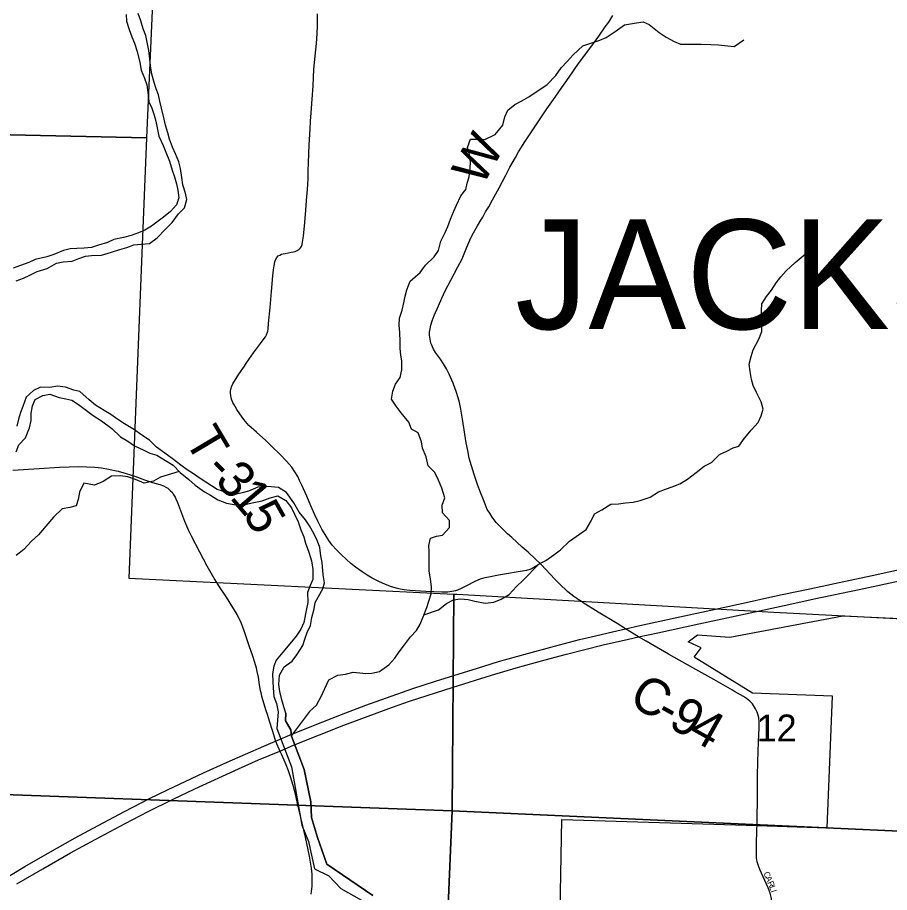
# Model space of a CAD drawing. Extents: x 0 to 34, y 0 to 22.
# Drawn here: x 3.441 to 4.796, y 18.381 to 19.741 of the extents above; entities that cross this region are included whole.
import ezdxf

# ---------------------------------------------------------------- set-up
doc = ezdxf.new("R2010")
doc.units = 0
for name, color, linetype in [('GM_X_City_Street', 7, 'Continuous'), ('GM_X_City_Street_Text', 7, 'Continuous'), ('GM_X_Corporation', 7, 'Continuous'), ('GM_X_County_Road', 7, 'Continuous'), ('GM_X_County_Road_Text', 7, 'Continuous'), ('GM_X_Minor_River', 7, 'Continuous'), ('GM_X_Section', 7, 'Continuous'), ('GM_X_Section_Text', 7, 'Continuous'), ('GM_X_State_Route', 7, 'Continuous'), ('GM_X_Township_Road', 7, 'Continuous'), ('GM_X_Township_Road_Text', 7, 'Continuous'), ('GM_X_Township_Text', 7, 'Continuous')]:
    doc.layers.add(name, color=color, linetype=linetype)

msp = doc.modelspace()

# ---------------------------------------------------------------- linework, layer by layer
at = {"layer": 'GM_X_City_Street'}
msp.add_lwpolyline([(4.6123, 18.3277), (4.6134, 18.3522), (4.6135, 18.3645), (4.6129, 18.3706), (4.6124, 18.3736), (4.6108, 18.3794), (4.6075, 18.388), (4.5998, 18.4049), (4.5947, 18.4162), (4.5925, 18.422), (4.5907, 18.4281), (4.5897, 18.4343), (4.5893, 18.4405), (4.5894, 18.453), (4.5903, 18.4799), (4.5904, 18.4842)], dxfattribs=at)
at = {"layer": 'GM_X_Corporation'}
msp.add_lwpolyline([(4.9748, 17.7073), (4.5871, 17.7299), (4.5956, 17.9659), (4.2619, 17.827), (4.283, 18.2672), (4.2872, 18.4939), (4.5904, 18.485), (4.6993, 18.4813), (4.7077, 18.686), (4.5833, 18.6907), (4.4929, 18.7467), (4.5036, 18.7609), (4.4834, 18.7705), (4.4977, 18.7812), (4.5483, 18.7776), (4.7237, 18.8109), (5.1009, 18.7931)], dxfattribs=at)
at = {"layer": 'GM_X_County_Road'}
for points in [[(4.2532, 18.8921), (4.2462, 18.899), (4.2348, 18.9095), (4.2255, 18.9177), (4.2095, 18.9324), (4.2028, 18.9381), (4.1936, 18.9471), (4.1851, 18.956), (4.1789, 18.964), (4.1749, 18.9701), (4.1712, 18.9761), (4.1676, 18.9842), (4.165, 18.991), (4.1605, 19.0026), (4.156, 19.0149), (4.151, 19.0302), (4.1467, 19.0439), (4.1431, 19.0559), (4.1407, 19.0676), (4.1385, 19.0798), (4.136, 19.093), (4.1327, 19.1162), (4.1298, 19.1318), (4.1278, 19.1421), (4.1261, 19.1495), (4.1234, 19.1581), (4.1224, 19.1609), (4.1214, 19.1638), (4.118, 19.1723), (4.1119, 19.1864), (4.1078, 19.1946), (4.1032, 19.2027), (4.0984, 19.2097), (4.0906, 19.2203), (4.0876, 19.2255), (4.0858, 19.2289), (4.0847, 19.2316), (4.0836, 19.2348), (4.0821, 19.241), (4.0815, 19.2471), (4.0815, 19.2517), (4.0821, 19.2569), (4.0835, 19.2627), (4.0857, 19.2695), (4.0887, 19.2775), (4.0953, 19.2928), (4.1006, 19.3046), (4.1059, 19.3158), (4.1145, 19.3327), (4.1256, 19.3533), (4.1319, 19.3656), (4.1391, 19.384), (4.1456, 19.3981), (4.1498, 19.4063), (4.1558, 19.4169), (4.1612, 19.426), (4.1642, 19.4307), (4.1686, 19.4385), (4.1733, 19.4465), (4.1794, 19.4573), (4.1895, 19.4759), (4.1947, 19.486), (4.1997, 19.4957), (4.2064, 19.5081), (4.2148, 19.5232), (4.2199, 19.5322), (4.2243, 19.5393), (4.2286, 19.5458), (4.2525, 19.5819), (4.2636, 19.5989), (4.2765, 19.6169), (4.2832, 19.6266), (4.2984, 19.6483), (4.3129, 19.6691), (4.332, 19.6947), (4.3444, 19.7119), (4.3545, 19.7263), (4.3599, 19.7336), (4.3632, 19.7387), (4.3662, 19.7441)], [(3.4336, 19.0374), (3.4746, 19.0397), (3.5064, 19.0416), (3.5362, 19.0427), (3.5489, 19.0424), (3.5612, 19.0418), (3.5714, 19.0406), (3.5825, 19.0389), (3.5973, 19.0355), (3.6097, 19.0322), (3.6236, 19.0277), (3.6385, 19.0221), (3.6506, 19.018), (3.6622, 19.015), (3.6678, 19.0129), (3.6717, 19.0108), (3.6744, 19.009), (3.6769, 19.0071), (3.6789, 19.005), (3.6812, 19.0027), (3.6831, 19.0001), (3.6858, 18.9952), (3.6872, 18.9924), (3.6897, 18.9867), (3.7008, 18.9577), (3.7068, 18.9434), (3.7109, 18.9351), (3.7238, 18.9103), (3.7355, 18.8884), (3.7475, 18.8668), (3.7535, 18.8572), (3.7653, 18.8395), (3.7738, 18.8264), (3.7818, 18.813), (3.7862, 18.8048), (3.7888, 18.7993), (3.793, 18.7877), (3.8011, 18.763), (3.8055, 18.7503), (3.8096, 18.7386), (3.8121, 18.7299), (3.813, 18.7244), (3.8148, 18.7153), (3.8168, 18.7034), (3.8184, 18.6945), (3.819, 18.6915), (3.8202, 18.6857), (3.8238, 18.674), (3.8264, 18.6652), (3.8293, 18.6564), (3.8319, 18.6475), (3.8367, 18.6329), (3.8402, 18.6211), (3.842, 18.6161), (3.8434, 18.6123), (3.8471, 18.6038), (3.8487, 18.6005), (3.8511, 18.5954), (3.8551, 18.587), (3.8582, 18.5796), (3.8617, 18.5704), (3.8649, 18.5609), (3.869, 18.5477), (3.872, 18.5359), (3.8757, 18.5191), (3.8882, 18.4664), (3.8941, 18.4369), (3.8972, 18.4185), (3.8982, 18.4092), (3.8985, 18.3999), (3.8982, 18.3905), (3.8969, 18.3781)], [(4.311, 18.837), (4.3102, 18.8375), (4.3059, 18.8407), (4.3012, 18.8443), (4.2964, 18.8482), (4.294, 18.8502), (4.2851, 18.8587), (4.2763, 18.8677), (4.255, 18.8903), (4.2532, 18.8921)], [(4.5522, 18.695), (4.5233, 18.7117), (4.4908, 18.7299), (4.4529, 18.7511), (4.418, 18.7712), (4.4064, 18.7781), (4.3993, 18.7823), (4.386, 18.7906), (4.3729, 18.7987), (4.3437, 18.8165), (4.3201, 18.8311), (4.3175, 18.8328), (4.3149, 18.8344), (4.3125, 18.8359), (4.311, 18.837)], [(4.5904, 18.4842), (4.5906, 18.4939), (4.591, 18.528), (4.5909, 18.5622), (4.5916, 18.5839), (4.5928, 18.615), (4.5939, 18.6367), (4.5938, 18.6459), (4.5931, 18.652), (4.5917, 18.6579), (4.5907, 18.6608), (4.5882, 18.6663), (4.585, 18.6715), (4.5832, 18.6739), (4.579, 18.6783), (4.5742, 18.682), (4.5691, 18.6855), (4.5551, 18.6933), (4.5522, 18.695)]]:
    msp.add_lwpolyline(points, dxfattribs=at)
at = {"layer": 'GM_X_Minor_River'}
for points in [[(3.6097, 19.7453), (3.6105, 19.7354), (3.6147, 19.7221), (3.6189, 19.7107), (3.6228, 19.7009), (3.627, 19.688), (3.6309, 19.6709), (3.6332, 19.6592), (3.6382, 19.6466), (3.642, 19.636), (3.644, 19.6208), (3.6452, 19.6095), (3.6497, 19.6), (3.6536, 19.589), (3.6559, 19.5795), (3.6606, 19.5564), (3.6674, 19.542), (3.6717, 19.5313), (3.677, 19.5173), (3.6813, 19.5033), (3.6851, 19.4934), (3.6882, 19.4824), (3.6901, 19.4726), (3.6917, 19.4604), (3.6883, 19.4498), (3.6789, 19.4391), (3.6679, 19.4303), (3.6494, 19.4166), (3.6388, 19.4101), (3.6289, 19.4063), (3.6179, 19.4021), (3.6058, 19.399), (3.5906, 19.3955), (3.5808, 19.3913), (3.5668, 19.3867), (3.5558, 19.3833), (3.5448, 19.3825), (3.5334, 19.3817), (3.5228, 19.3813), (3.5126, 19.3786), (3.4974, 19.3724), (3.4868, 19.369), (3.4682, 19.3644), (3.4584, 19.3598), (3.4459, 19.3552), (3.4345, 19.3514)], [(3.4388, 19.3316), (3.4501, 19.3358), (3.4604, 19.3404), (3.4717, 19.3458), (3.4869, 19.3508), (3.5016, 19.3588), (3.5122, 19.3611), (3.5259, 19.3623), (3.5361, 19.3661), (3.5467, 19.3696), (3.5562, 19.3711), (3.5718, 19.3716), (3.5873, 19.3762), (3.5998, 19.3804), (3.6108, 19.3835), (3.6218, 19.3877), (3.6332, 19.3885), (3.6464, 19.3896), (3.6582, 19.3984), (3.6714, 19.4125), (3.6812, 19.4224), (3.6914, 19.4354), (3.7005, 19.4449), (3.7042, 19.4578), (3.7023, 19.4677), (3.6977, 19.4809), (3.6965, 19.4919), (3.6942, 19.506), (3.6915, 19.5166), (3.6865, 19.5287), (3.6819, 19.5393), (3.6773, 19.5519), (3.6749, 19.5617), (3.6711, 19.5735), (3.6688, 19.583), (3.6649, 19.5997), (3.6622, 19.6107), (3.6599, 19.6205), (3.6565, 19.63), (3.6534, 19.6399), (3.6499, 19.6528), (3.6476, 19.6657), (3.6468, 19.6767), (3.6452, 19.6896), (3.6433, 19.6998), (3.6402, 19.7127), (3.6363, 19.7233), (3.6325, 19.7355), (3.6287, 19.7472)], [(4.3338, 19.7017), (4.3459, 19.7056), (4.3558, 19.7098), (4.3698, 19.7189), (4.3842, 19.7292), (4.3936, 19.7312), (4.4031, 19.7327), (4.4134, 19.7339), (4.4229, 19.7301), (4.4381, 19.7173), (4.4491, 19.7105), (4.4617, 19.7033), (4.4712, 19.6995), (4.5038, 19.6996), (4.5186, 19.6989), (4.5304, 19.6982)], [(3.8946, 18.6619), (3.9059, 18.6718), (3.9134, 18.6863), (3.9187, 18.6977), (3.9247, 18.7114), (3.9391, 18.7183), (3.9509, 18.7202), (3.9626, 18.7229), (3.9729, 18.7222), (3.9824, 18.7211), (3.9918, 18.7215), (4.0036, 18.7242), (4.0183, 18.7345), (4.0274, 18.7448), (4.0342, 18.7546), (4.0425, 18.7657), (4.0516, 18.7782), (4.061, 18.7878), (4.0666, 18.798), (4.0715, 18.8094), (4.0772, 18.8235), (4.0802, 18.8334), (4.0839, 18.8448), (4.0846, 18.8554), (4.083, 18.8683), (4.0807, 18.8801), (4.0807, 18.8972), (4.081, 18.9105), (4.0802, 18.9203), (4.0828, 18.9317), (4.0923, 18.9348), (4.1017, 18.9363), (4.1123, 18.9478), (4.1126, 18.9588), (4.1016, 18.9709), (4.1012, 18.9827), (4.1049, 18.9941), (4.1003, 19.0092), (4.0953, 19.0217), (4.0896, 19.0335), (4.0793, 19.0441), (4.0762, 19.0581), (4.0704, 19.0714), (4.0689, 19.0813), (4.0635, 19.0953), (4.0532, 19.1009), (4.049, 19.1116), (4.0372, 19.1263), (4.0296, 19.1366), (4.0223, 19.1475), (4.0242, 19.1601), (4.0283, 19.1711), (4.0355, 19.181), (4.0384, 19.1932), (4.0384, 19.2068), (4.0368, 19.2163), (4.0357, 19.2262), (4.0356, 19.2372), (4.0352, 19.2512), (4.034, 19.2626), (4.0347, 19.2732), (4.0388, 19.2858), (4.0414, 19.2972), (4.0437, 19.3074), (4.0463, 19.3177), (4.0515, 19.331), (4.0667, 19.3443), (4.075, 19.3558), (4.0886, 19.3687), (4.0953, 19.3786), (4.0991, 19.3931), (4.1059, 19.4064), (4.1096, 19.4159), (4.1141, 19.4276), (4.119, 19.4398), (4.1235, 19.4493), (4.1299, 19.4634), (4.1378, 19.4733), (4.1397, 19.4832), (4.1431, 19.4934), (4.1445, 19.5067), (4.1452, 19.5166), (4.1433, 19.5276), (4.1406, 19.539), (4.1451, 19.5519), (4.155, 19.5515), (4.1675, 19.5512), (4.1834, 19.5592), (4.1951, 19.5737), (4.1985, 19.5862), (4.203, 19.5969), (4.2139, 19.6057), (4.2249, 19.6114), (4.2359, 19.6175), (4.2643, 19.6366), (4.2775, 19.6507), (4.2862, 19.6628), (4.2952, 19.6727), (4.3047, 19.683), (4.3198, 19.6967), (4.3338, 19.7017)], [(4.5304, 19.6982), (4.5548, 19.6956), (4.5699, 19.7059)], [(4.5534, 19.0719), (4.562, 19.0745), (4.5707, 19.0871), (4.582, 19.1), (4.5922, 19.1114), (4.5967, 19.1217), (4.6, 19.1319), (4.5966, 19.1433), (4.5893, 19.1577), (4.5843, 19.1687), (4.582, 19.1782), (4.5797, 19.1907), (4.5781, 19.2021), (4.5815, 19.2138), (4.5845, 19.2241), (4.5931, 19.2408), (4.598, 19.2526), (4.5979, 19.2651), (4.5971, 19.275), (4.5971, 19.2848), (4.5978, 19.2955), (4.6053, 19.3072), (4.6129, 19.3171), (4.62, 19.3282), (4.6271, 19.3377), (4.6358, 19.3472), (4.6498, 19.3598), (4.6652, 19.3731), (4.6777, 19.3841)], [(3.8582, 18.6595), (3.8551, 18.669), (3.8516, 18.68), (3.8485, 18.6933), (3.8473, 18.7039), (3.8484, 18.7187), (3.8556, 18.7313), (3.8681, 18.7404), (3.8749, 18.7499), (3.8843, 18.7644), (3.8877, 18.7743), (3.891, 18.7849), (3.8963, 18.7959), (3.8985, 18.8081), (3.9023, 18.8214), (3.9037, 18.8313), (3.9086, 18.8408), (3.9158, 18.8526), (3.918, 18.8621), (3.9161, 18.8746), (3.9145, 18.8936), (3.9125, 18.9038), (3.911, 18.9167), (3.9071, 18.927), (3.9018, 18.9387), (3.8949, 18.9505), (3.8884, 18.9599), (3.8789, 18.9717), (3.8705, 18.9864), (3.859, 19.0024), (3.8465, 19.0103), (3.8354, 19.0114), (3.8244, 19.0117), (3.8146, 19.0106), (3.8002, 19.0044), (3.79, 19.0017), (3.7767, 18.999), (3.7649, 19.0028), (3.7512, 19.0069), (3.725, 19.0243), (3.7147, 19.0315), (3.7048, 19.0379), (3.6949, 19.0447), (3.6816, 19.0553), (3.6702, 19.0636), (3.6572, 19.0731), (3.6462, 19.084), (3.6325, 19.0927), (3.6226, 19.0999), (3.6074, 19.109), (3.5971, 19.1158), (3.5861, 19.1237), (3.5758, 19.1301), (3.5621, 19.1384), (3.5522, 19.1464), (3.5381, 19.1592), (3.5286, 19.1615), (3.5157, 19.166), (3.5032, 19.1678), (3.4914, 19.1659), (3.4766, 19.1662), (3.4657, 19.1609)], [(3.4387, 19.0659), (3.4429, 19.0765), (3.4534, 19.0872), (3.4594, 19.1028), (3.4621, 19.1142), (3.4624, 19.1256), (3.4642, 19.137), (3.4687, 19.1468), (3.4805, 19.1533), (3.4911, 19.1553), (3.5059, 19.15), (3.5162, 19.1478), (3.5257, 19.1459), (3.5356, 19.1391), (3.5481, 19.13), (3.5584, 19.1221), (3.5717, 19.1138), (3.5877, 19.1017), (3.601, 19.0892), (3.6124, 19.0824), (3.6227, 19.0748), (3.6372, 19.0681), (3.6467, 19.0635), (3.6573, 19.0605), (3.671, 19.0522), (3.6828, 19.045), (3.6938, 19.0333), (3.7072, 19.0227), (3.7171, 19.014), (3.7315, 19.0034), (3.741, 18.9982), (3.7524, 18.991), (3.7657, 18.9857), (3.7802, 18.9831), (3.7923, 18.9831), (3.8056, 18.9866), (3.8211, 18.9897), (3.8336, 18.9939), (3.8458, 18.997), (3.8579, 18.9902), (3.8671, 18.9785), (3.8717, 18.969), (3.877, 18.9569), (3.8816, 18.9443), (3.8862, 18.9333), (3.8886, 18.9239), (3.8939, 18.9095), (3.8978, 18.8962), (3.9001, 18.8825), (3.8998, 18.8673), (3.896, 18.8578), (3.8919, 18.8472), (3.892, 18.8316), (3.8901, 18.8214), (3.886, 18.8005), (3.8815, 18.7898), (3.874, 18.7792), (3.8642, 18.767), (3.8532, 18.754), (3.843, 18.7419), (3.8393, 18.7324), (3.8374, 18.7206), (3.8378, 18.7088), (3.8386, 18.6986), (3.8395, 18.6853), (3.8433, 18.6743), (3.846, 18.6614)], [(3.4657, 19.1609), (3.4543, 19.1506), (3.4494, 19.1361), (3.4457, 19.1266), (3.4427, 19.1164), (3.4401, 19.1054)], [(4.0726, 18.8122), (4.0954, 18.8201), (4.1075, 18.8301), (4.1185, 18.8354), (4.1291, 18.837), (4.1412, 18.8359), (4.1519, 18.8336), (4.1678, 18.8306), (4.1815, 18.8322), (4.1928, 18.8364), (4.2049, 18.8441), (4.2167, 18.8562), (4.2265, 18.8658), (4.2518, 18.8913), (4.262, 18.8966), (4.2745, 18.9058), (4.2847, 18.9134), (4.2991, 18.9267), (4.3248, 18.9451), (4.3323, 18.9576), (4.3376, 18.9694), (4.349, 18.9755), (4.3633, 18.9843), (4.3751, 18.9847), (4.3857, 18.9863), (4.3979, 18.9874), (4.4085, 18.9901), (4.4244, 18.9951), (4.4372, 19.0035), (4.4482, 19.0077), (4.4585, 19.0112), (4.4702, 19.0158), (4.4823, 19.0234), (4.4956, 19.0333), (4.508, 19.0432), (4.5194, 19.049), (4.5322, 19.0615), (4.5432, 19.0665), (4.5534, 19.0719)], [(3.6923, 19.0349), (3.6631, 19.0264), (3.6522, 19.0203), (3.6381, 19.0172), (3.6244, 19.0225), (3.6123, 19.0266), (3.6009, 19.0281), (3.5872, 19.028), (3.574, 19.0196), (3.5607, 19.0139), (3.544, 19.0169), (3.5376, 19.0032), (3.5354, 18.9914), (3.5324, 18.9819), (3.5222, 18.9792), (3.5104, 18.9773), (3.4972, 18.9639), (3.4851, 18.9502), (3.4734, 18.9365), (3.4628, 18.927), (3.4507, 18.9137), (3.439, 18.9045)], [(3.846, 18.6614), (3.844, 18.6355), (3.867, 18.5761), (3.8828, 18.4854), (3.8931, 18.4597), (3.9027, 18.4172), (3.9247, 18.4067), (3.9437, 18.387), (3.9756, 18.3689)], [(3.9934, 18.3758), (3.9216, 18.4249), (3.9075, 18.4662), (3.8979, 18.4973), (3.8967, 18.5215), (3.8867, 18.5716), (3.8668, 18.6235), (3.8656, 18.6333), (3.8576, 18.6477), (3.8582, 18.6595)], [(3.8582, 18.6595), (3.8576, 18.6477), (3.8656, 18.6333), (3.8668, 18.6235), (3.8867, 18.5716), (3.8967, 18.5215), (3.8979, 18.4973), (3.9075, 18.4662), (3.9216, 18.4249), (3.9934, 18.3758)], [(3.8946, 18.6619), (3.8667, 18.6248)]]:
    msp.add_lwpolyline(points, dxfattribs=at)
at = {"layer": 'GM_X_Section'}
for points in [[(3.1703, 20.5686), (3.6876, 20.5473), (3.6799, 20.3833), (3.6562, 19.8796), (3.6414, 19.554), (3.1241, 19.5651)], [(3.1241, 19.5651), (3.6414, 19.554), (3.6343, 19.3746), (3.6142, 18.8692), (4.1194, 18.8444), (4.1166, 18.5074), (3.0927, 18.5447)], [(4.1194, 18.8444), (4.1236, 18.8442), (4.6166, 18.8164), (5.1167, 18.7903), (5.1294, 18.7895), (5.1195, 18.4619), (4.1166, 18.5074)], [(4.1166, 18.5074), (4.0746, 17.5111), (3.0654, 17.5504), (3.0927, 18.5447)], [(4.1166, 18.5074), (5.1195, 18.4619), (5.0805, 17.4591), (4.0746, 17.5111)]]:
    msp.add_lwpolyline(points, close=True, dxfattribs=at)
at = {"layer": 'GM_X_State_Route'}
for points in [[(3.4125, 18.3974), (3.4525, 18.4212), (3.4874, 18.4415), (3.5308, 18.4658), (3.5663, 18.485), (3.6075, 18.5067), (3.6462, 18.5265), (3.674, 18.5403), (3.7301, 18.5668), (3.7669, 18.5834), (3.8237, 18.6083), (3.842, 18.6161), (3.8637, 18.6253), (3.9012, 18.6403), (3.9445, 18.6573), (3.9823, 18.6716), (4.0144, 18.6832), (4.0555, 18.6975), (4.0909, 18.7092), (4.1561, 18.7295), (4.1888, 18.7395), (4.2335, 18.7524), (4.2755, 18.7637), (4.3146, 18.7738), (4.3327, 18.7782), (4.3659, 18.7861), (4.386, 18.7906), (4.4083, 18.7956), (4.4629, 18.8075), (4.5448, 18.8252), (4.5781, 18.8325), (4.6054, 18.8386), (4.6296, 18.8438), (4.6722, 18.8528), (4.7178, 18.8625), (4.7694, 18.8735), (4.8423, 18.8894)], [(3.4401, 18.3941), (3.4803, 18.4176), (3.5236, 18.4421), (3.5617, 18.4631), (3.6083, 18.488), (3.6442, 18.5065), (3.6831, 18.5259), (3.7167, 18.542), (3.7844, 18.573), (3.8157, 18.5867), (3.8487, 18.6005), (3.8701, 18.6095), (3.9104, 18.6259), (3.948, 18.6406), (3.9858, 18.6548), (4.0238, 18.6686), (4.0502, 18.6779), (4.1181, 18.7), (4.1775, 18.7185), (4.2162, 18.7299), (4.2611, 18.7424), (4.2942, 18.751), (4.3514, 18.7654), (4.3907, 18.7747), (4.4064, 18.7781), (4.4363, 18.7845), (4.5, 18.7982), (4.594, 18.8187), (4.6396, 18.8285), (4.6791, 18.8369), (4.749, 18.8519), (4.8188, 18.8669)]]:
    msp.add_lwpolyline(points, dxfattribs=at)
at = {"layer": 'GM_X_Township_Road'}
msp.add_lwpolyline([(4.2532, 18.8921), (4.2496, 18.8897), (4.2437, 18.8859), (4.2409, 18.8842), (4.237, 18.8826), (4.2323, 18.8812), (4.2162, 18.8786), (4.2039, 18.8765), (4.1886, 18.8739), (4.1734, 18.8709), (4.1675, 18.8696), (4.1603, 18.8676), (4.1518, 18.8639), (4.1389, 18.8571), (4.1304, 18.853), (4.1247, 18.8507), (4.1219, 18.8496), (4.1189, 18.8489), (4.1159, 18.8483), (4.1097, 18.8477), (4.1004, 18.8476), (4.0756, 18.8486), (4.0508, 18.8503), (4.0418, 18.8512), (4.0357, 18.8522), (4.0296, 18.8536), (4.0207, 18.8564), (4.012, 18.8597), (4.0035, 18.8635), (3.9924, 18.8692), (3.9844, 18.8738), (3.9765, 18.8789), (3.9665, 18.8862), (3.9592, 18.8921), (3.9523, 18.8982), (3.9436, 18.9064), (3.9368, 18.9133), (3.9302, 18.9207), (3.9247, 18.928), (3.919, 18.9371), (3.9139, 18.9457), (3.9076, 18.9577), (3.9029, 18.9675), (3.8968, 18.9818), (3.8907, 18.9967), (3.8828, 19.0138), (3.8795, 19.0212), (3.8765, 19.0271), (3.8721, 19.0346), (3.8673, 19.0418), (3.8589, 19.0512), (3.8485, 19.0618), (3.8367, 19.0734), (3.8267, 19.0834), (3.8122, 19.0961), (3.8005, 19.1066), (3.793, 19.1159), (3.7867, 19.1246), (3.7821, 19.1314), (3.7792, 19.1363), (3.7773, 19.1397), (3.7757, 19.1426), (3.7748, 19.1449), (3.7736, 19.1477), (3.7729, 19.15), (3.7724, 19.1531), (3.772, 19.1566), (3.772, 19.1599), (3.7734, 19.1666), (3.7757, 19.1715), (3.7851, 19.1863), (3.7936, 19.1989), (3.7968, 19.2042), (3.8077, 19.2193), (3.8189, 19.2342), (3.8242, 19.2419), (3.8262, 19.2445), (3.8279, 19.2473), (3.8292, 19.2503), (3.8299, 19.2531), (3.8304, 19.2564), (3.8313, 19.2653), (3.8339, 19.29), (3.836, 19.3148), (3.8379, 19.3395), (3.8387, 19.3487), (3.8397, 19.3548), (3.8403, 19.3586), (3.8412, 19.3611), (3.8421, 19.364), (3.844, 19.3675), (3.8463, 19.3702), (3.8485, 19.3716), (3.8513, 19.373), (3.8541, 19.3734), (3.857, 19.3742), (3.8663, 19.3759), (3.8699, 19.3764), (3.8728, 19.3772), (3.8758, 19.3785), (3.8786, 19.3806), (3.8807, 19.3826), (3.8825, 19.385), (3.8835, 19.388), (3.8842, 19.3917), (3.8844, 19.3947), (3.8853, 19.4008), (3.8875, 19.4224), (3.8889, 19.4411), (3.8904, 19.4564), (3.8917, 19.4733), (3.8927, 19.49), (3.893, 19.5023), (3.8933, 19.5147), (3.8944, 19.5427), (3.8957, 19.5675), (3.8963, 19.5799), (3.8973, 19.5928), (3.8992, 19.6138), (3.9005, 19.6346), (3.9018, 19.6604), (3.9036, 19.6809), (3.9055, 19.7004), (3.9066, 19.7158), (3.9071, 19.7281), (3.9075, 19.7464)], dxfattribs=at)

# ---------------------------------------------------------------- texts
at = {"layer": 'GM_X_City_Street_Text'}
for s, rotation, p in [('C', 292.816, (4.6001, 18.4107)), ('A', 292.8183, (4.603, 18.4038)), ('R', 292.717, (4.6063, 18.3961)), ('L', 290.2842, (4.6091, 18.3893)), ('I', 288.3658, (4.6114, 18.3831))]:
    msp.add_text(s, height=0.00947, rotation=rotation, dxfattribs=at).set_placement(p)
at = {"layer": 'GM_X_County_Road_Text'}
for s, rotation, p in [('W', 60.5261, (4.1631, 19.4766)), ('C', 329.3716, (4.3886, 18.675)), ('9', 330.8024, (4.4504, 18.639)), ('-', 330.791, (4.4301, 18.6504)), ('4', 330.8151, (4.481, 18.622))]:
    msp.add_text(s, height=0.0568, rotation=rotation, dxfattribs=at).set_placement(p)
at = {"layer": 'GM_X_Section_Text'}
msp.add_text('12', height=0.04186, rotation=0, dxfattribs=at).set_placement((4.5897, 18.6154))
at = {"layer": 'GM_X_Township_Road_Text'}
for s, rotation, p in [('T', 300.7411, (3.6996, 19.0842)), ('-', 314.2634, (3.7302, 19.0361)), ('3', 312.6626, (3.7462, 19.0197)), ('1', 310.34, (3.7695, 18.9945)), ('5', 299.3544, (3.7905, 18.9701))]:
    msp.add_text(s, height=0.0568, rotation=rotation, dxfattribs=at).set_placement(p)
at = {"layer": 'GM_X_Township_Text'}
msp.add_text('JACKSON', height=0.17045, rotation=0, dxfattribs=at).set_placement((4.2144, 19.2564))

doc.saveas('drawing.dxf')
